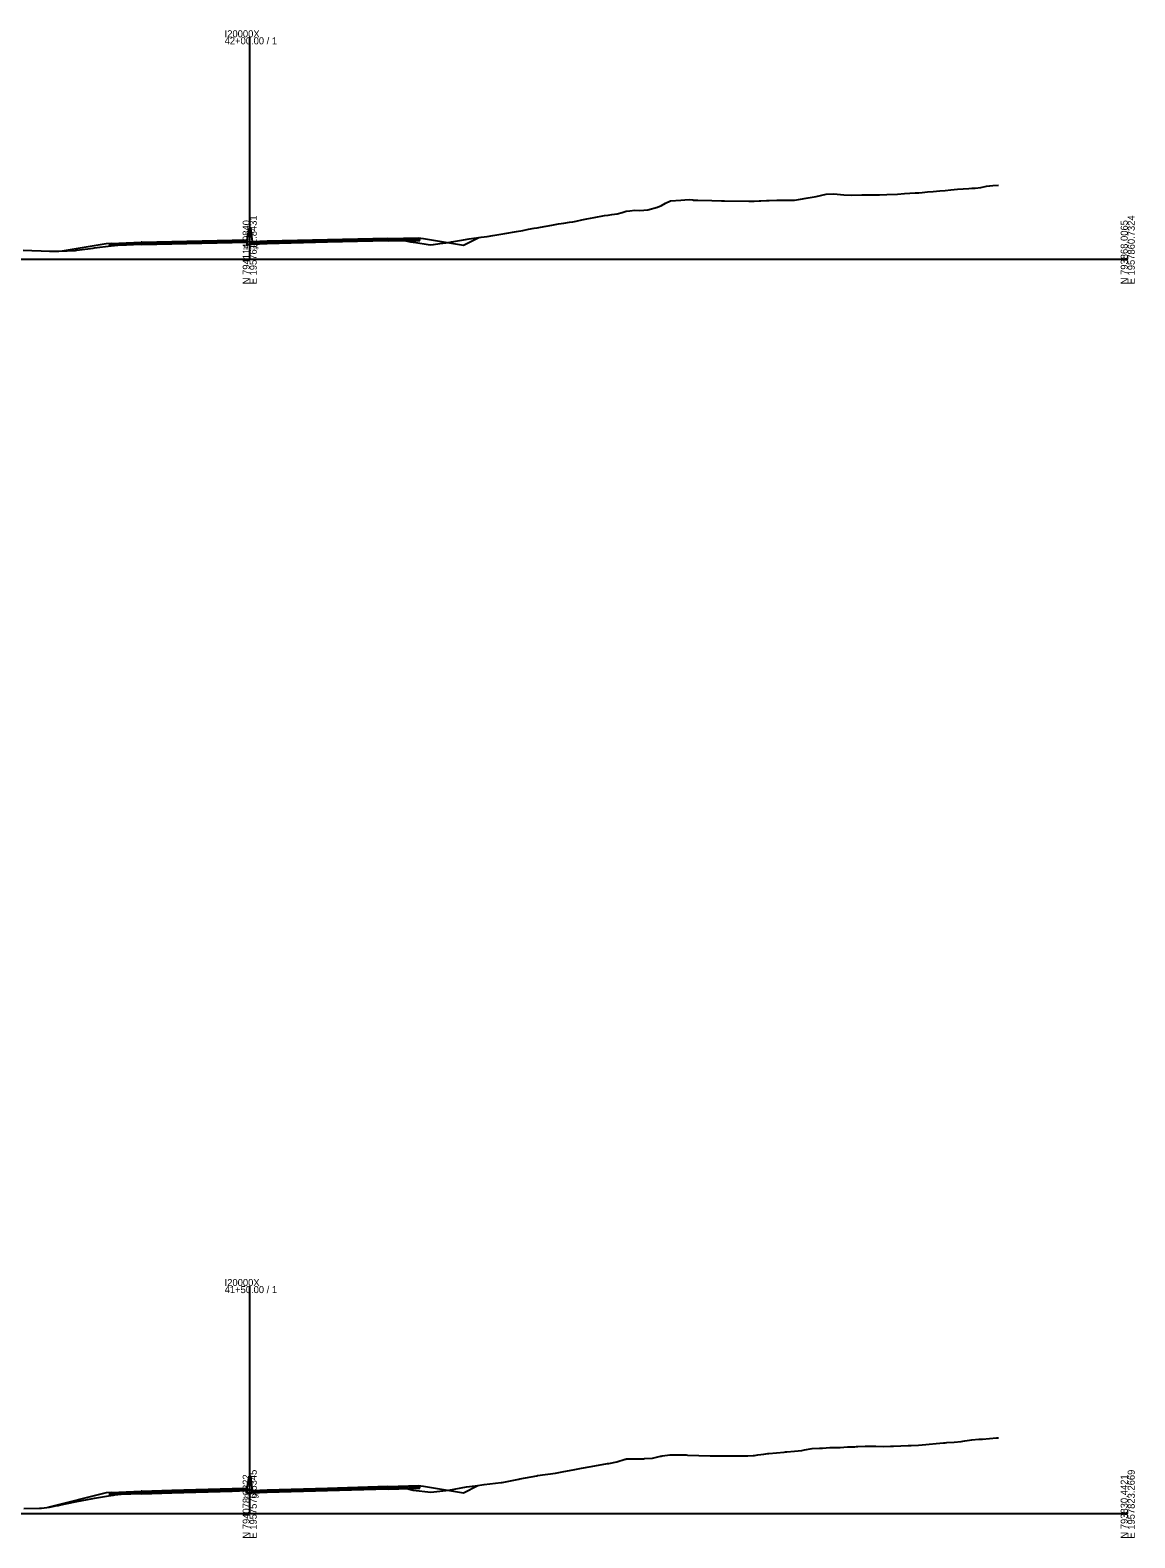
# Model space of a CAD drawing. Extents: x -4026 to 9638, y -10 to 19609.
# Drawn here: x -2738 to -2297, y 11490 to 12091 of the extents above; entities that cross this region are included whole.
import ezdxf

# ---------------------------------------------------------------- set-up
doc = ezdxf.new("R2010")
doc.units = 0
for name, color, linetype in [('RD_GPK_XS_Cell', 7, 'Continuous'), ('RD_XS_Base', 7, 'Continuous'), ('RD_XS_ExGround', 7, 'Continuous'), ('RD_XS_Greenside', 7, 'Continuous'), ('RD_XS_MedBWall', 7, 'Continuous'), ('RD_XS_Pave', 7, 'Continuous'), ('RD_XS_PaveOvlay', 7, 'Continuous'), ('RD_XS_TieSlope', 7, 'Continuous'), ('RD_XS_TX_Elev_EX', 7, 'Continuous')]:
    doc.layers.add(name, color=color, linetype=linetype)

msp = doc.modelspace()

# ---------------------------------------------------------------- linework, layer by layer
at = {"layer": 'RD_GPK_XS_Cell'}
for p, q in [((-2650, 12000), (-2650, 12088.48)), ((-3000, 12000), (-2650, 12000)), ((-2650, 12000), (-2300, 12000)), ((-2650, 11500), (-2650, 11590.67)), ((-3000, 11500), (-2650, 11500)), ((-2650, 11500), (-2300, 11500))]:
    msp.add_line(p, q, dxfattribs=at)
at = {"layer": 'RD_XS_Base'}
for points in [[(-2705.75, 12005.99), (-2705.25, 12006.01), (-2693.25, 12006.48)], [(-2705.75, 12005.32), (-2705.75, 12005.99)], [(-2693.25, 12005.81), (-2705.75, 12005.32)], [(-2693.25, 12006.48), (-2693, 12006.49)], [(-2693.25, 12005.81), (-2693.25, 12006.48)], [(-2693, 12005.82), (-2693.25, 12005.81)], [(-2657, 12007.33), (-2681, 12006.78), (-2693, 12006.49)], [(-2693, 12005.82), (-2681, 12006.11), (-2657, 12006.66)], [(-2693, 12006.49), (-2693, 12005.82)], [(-2651, 12007.43), (-2657, 12007.33)], [(-2657, 12007.33), (-2657, 12006.66)], [(-2657, 12006.66), (-2651, 12006.76)], [(-2651, 12006.76), (-2651, 12007.43)], [(-2649, 12006.61), (-2643, 12006.86)], [(-2649, 12005.94), (-2649, 12006.61)], [(-2643, 12006.19), (-2649, 12005.94)], [(-2643, 12006.86), (-2619, 12007.42), (-2595, 12007.98)], [(-2595, 12007.31), (-2619, 12006.75), (-2643, 12006.19)], [(-2643, 12006.19), (-2643, 12006.86)], [(-2595, 12007.98), (-2594.75, 12007.98)], [(-2595, 12007.31), (-2595, 12007.98)], [(-2594.75, 12007.31), (-2595, 12007.31)], [(-2582.25, 12008.17), (-2582.75, 12008.16), (-2594.75, 12007.98)], [(-2594.75, 12007.98), (-2594.75, 12007.31)], [(-2594.75, 12007.31), (-2582.25, 12007.5)], [(-2582.25, 12007.5), (-2582.25, 12008.17)], [(-2657, 11509.65), (-2681, 11508.94), (-2693, 11508.57)], [(-2651, 11509.84), (-2657, 11509.65)], [(-2657, 11509.65), (-2657, 11508.98)], [(-2651, 11509.17), (-2651, 11509.84)], [(-2643, 11508.99), (-2619, 11509.71), (-2595, 11510.43)], [(-2595, 11509.76), (-2619, 11509.04), (-2643, 11508.32)], [(-2595, 11510.43), (-2594.75, 11510.43)], [(-2595, 11509.76), (-2595, 11510.43)], [(-2594.75, 11509.76), (-2595, 11509.76)], [(-2582.25, 11510.81), (-2582.75, 11510.8), (-2594.75, 11510.43)], [(-2594.75, 11510.43), (-2594.75, 11509.76)], [(-2594.75, 11509.76), (-2582.25, 11510.14)], [(-2582.25, 11510.14), (-2582.25, 11510.81)], [(-2705.75, 11508.07), (-2705.25, 11508.09), (-2693.25, 11508.56)], [(-2705.75, 11507.4), (-2705.75, 11508.07)], [(-2693.25, 11507.89), (-2705.75, 11507.4)], [(-2693.25, 11508.56), (-2693, 11508.57)], [(-2693.25, 11507.89), (-2693.25, 11508.56)], [(-2693, 11507.9), (-2693.25, 11507.89)], [(-2693, 11507.9), (-2681, 11508.27), (-2657, 11508.98)], [(-2693, 11508.57), (-2693, 11507.9)], [(-2657, 11508.98), (-2651, 11509.17)], [(-2649, 11508.74), (-2643, 11508.99)], [(-2649, 11508.07), (-2649, 11508.74)], [(-2643, 11508.32), (-2649, 11508.07)], [(-2643, 11508.32), (-2643, 11508.99)]]:
    msp.add_lwpolyline(points, dxfattribs=at)
at = {"layer": 'RD_XS_ExGround'}
for points in [[(-2740.27, 12003.64), (-2736.88, 12003.55), (-2733.16, 12003.41), (-2729.8, 12003.28), (-2726.05, 12003.19), (-2719.46, 12003.54), (-2718.93, 12003.6), (-2712.43, 12004.45), (-2711.82, 12004.53), (-2705.4, 12005.39), (-2705.06, 12005.43), (-2704.33, 12005.47), (-2703.92, 12005.5), (-2702.52, 12005.57), (-2699.07, 12005.74), (-2693.47, 12005.99), (-2689.83, 12006.16), (-2679.66, 12006.47), (-2678.88, 12006.49), (-2677.9, 12006.52), (-2667.07, 12006.81), (-2658.95, 12007.01), (-2655.28, 12007.1), (-2650, 12006.96), (-2649.67, 12006.95), (-2649.31, 12006.92), (-2645.65, 12006.63), (-2641.31, 12006.92), (-2640.52, 12006.97), (-2635.69, 12007.12), (-2628.35, 12007.34), (-2622.45, 12007.49), (-2616.83, 12007.64), (-2614.55, 12007.7), (-2605.28, 12007.93), (-2599.83, 12007.97), (-2597.12, 12007.99), (-2595.29, 12007.92), (-2593.96, 12007.86), (-2593.38, 12007.84), (-2591.92, 12007.77), (-2590.93, 12007.68), (-2588.38, 12007.48), (-2585.87, 12006.99), (-2584.85, 12006.8), (-2583.81, 12006.63), (-2578.83, 12005.93), (-2577.77, 12005.75), (-2576.7, 12005.94), (-2574.24, 12006.25), (-2571.8, 12006.58), (-2570.7, 12006.73), (-2569.59, 12006.92), (-2567.17, 12007.3), (-2564.77, 12007.68), (-2562.48, 12008.09), (-2557.74, 12008.83), (-2556.56, 12008.94), (-2555.37, 12009.11), (-2553.03, 12009.48), (-2550.71, 12009.83), (-2548.26, 12010.26), (-2543.68, 12011.02), (-2541.14, 12011.47), (-2538.88, 12011.94), (-2536.65, 12012.33), (-2535.35, 12012.56), (-2534.03, 12012.79), (-2531.81, 12013.22), (-2529.62, 12013.61), (-2526.92, 12014.06), (-2524.74, 12014.38), (-2522.58, 12014.74), (-2521.2, 12014.95), (-2519.81, 12015.24), (-2517.67, 12015.66), (-2515.55, 12016.09), (-2512.7, 12016.64), (-2508.52, 12017.38), (-2507.06, 12017.61), (-2505.59, 12017.8), (-2503.53, 12018.11), (-2501.49, 12018.69), (-2499.99, 12019.13), (-2498.48, 12019.28), (-2496.46, 12019.51), (-2494.46, 12019.49), (-2492.92, 12019.5), (-2491.36, 12019.67), (-2487.43, 12020.71), (-2485.85, 12021.43), (-2484.25, 12022.29), (-2482.31, 12023.24), (-2478.17, 12023.57), (-2476.53, 12023.7), (-2474.53, 12023.84), (-2473.39, 12023.67), (-2473.07, 12023.61), (-2471.32, 12023.57), (-2465.74, 12023.42), (-2461.96, 12023.32), (-2460.78, 12023.29), (-2450.98, 12023.16), (-2448.91, 12023.12), (-2446.96, 12023.25), (-2446.24, 12023.3), (-2444.02, 12023.42), (-2442.9, 12023.46), (-2439.89, 12023.59), (-2438.21, 12023.6), (-2436.35, 12023.56), (-2434.47, 12023.56), (-2432.82, 12023.6), (-2431.18, 12023.88), (-2427.36, 12024.47), (-2424.15, 12024.96), (-2420.25, 12025.9), (-2417.12, 12026.12), (-2413.14, 12025.64), (-2410.08, 12025.55), (-2406.02, 12025.63), (-2403.05, 12025.63), (-2398.91, 12025.64), (-2396.02, 12025.75), (-2391.8, 12025.96), (-2388.99, 12026.15), (-2384.69, 12026.44), (-2383.32, 12026.53), (-2381.96, 12026.62), (-2379.78, 12026.84), (-2377.58, 12027.03), (-2376.25, 12027.17), (-2374.93, 12027.27), (-2372.71, 12027.45), (-2370.47, 12027.66), (-2369.17, 12027.77), (-2367.9, 12027.89), (-2365.64, 12028.05), (-2363.35, 12028.22), (-2362.1, 12028.3), (-2360.87, 12028.38), (-2358.57, 12028.56), (-2356.24, 12029.09), (-2355.03, 12029.31), (-2353.83, 12029.4), (-2351.5, 12029.49)], [(-2740.05, 11501.99), (-2733.81, 11502.11), (-2733.41, 11502.09), (-2733, 11502.13), (-2729.87, 11502.54), (-2726.72, 11503.17), (-2726.33, 11503.26), (-2725.95, 11503.33), (-2719.63, 11504.62), (-2718.9, 11504.75), (-2712.54, 11505.96), (-2711.85, 11506.09), (-2705.44, 11507.24), (-2705.12, 11507.28), (-2704.32, 11507.36), (-2703.73, 11507.41), (-2699.99, 11507.79), (-2699.18, 11507.87), (-2697.85, 11507.93), (-2689.71, 11508.31), (-2678.92, 11508.66), (-2667.23, 11508.99), (-2666.89, 11509), (-2666.52, 11509.01), (-2655.3, 11509.29), (-2652.01, 11509.26), (-2650, 11509.25), (-2649.7, 11509.24), (-2648.1, 11509.09), (-2645.69, 11508.88), (-2642.04, 11509.13), (-2640.54, 11509.24), (-2634.34, 11509.44), (-2628.32, 11509.63), (-2624.94, 11509.71), (-2616.77, 11509.92), (-2608.81, 11510.15), (-2605.33, 11510.25), (-2603, 11510.28), (-2597.07, 11510.35), (-2591.96, 11510.49), (-2588.45, 11510.22), (-2584.87, 11509.38), (-2577.77, 11508.58), (-2570.68, 11509.26), (-2563.59, 11510.68), (-2560.16, 11510.98), (-2556.5, 11511.56), (-2549.71, 11512.37), (-2549.4, 11512.41), (-2542.66, 11513.76), (-2542.31, 11513.82), (-2535.61, 11515.04), (-2535.22, 11515.1), (-2528.13, 11516.11), (-2524.81, 11516.71), (-2521.03, 11517.41), (-2517.74, 11518.11), (-2513.94, 11518.81), (-2507.41, 11519.9), (-2506.85, 11519.98), (-2503.59, 11520.56), (-2500.36, 11521.64), (-2500.06, 11521.71), (-2499.75, 11521.74), (-2493.31, 11521.85), (-2492.99, 11521.87), (-2492.66, 11521.91), (-2489.45, 11522.08), (-2486.26, 11522.86), (-2485.92, 11522.93), (-2485.57, 11522.98), (-2482.38, 11523.42), (-2478.03, 11523.44), (-2477.16, 11523.42), (-2475.96, 11523.34), (-2475.47, 11523.29), (-2466.46, 11523.06), (-2462.88, 11522.97), (-2455.39, 11522.95), (-2451.38, 11522.95), (-2449.34, 11523.12), (-2448.82, 11523.17), (-2447.51, 11523.36), (-2445.06, 11523.73), (-2444.21, 11523.85), (-2443.49, 11523.95), (-2443.01, 11523.99), (-2436.91, 11524.49), (-2436.42, 11524.54), (-2435.92, 11524.6), (-2432.88, 11524.91), (-2429.87, 11525.19), (-2428.83, 11525.35), (-2425.81, 11525.92), (-2422.82, 11526.08), (-2422.28, 11526.11), (-2421.73, 11526.11), (-2418.74, 11526.32), (-2415.77, 11526.32), (-2415.21, 11526.34), (-2414.64, 11526.35), (-2411.67, 11526.55), (-2408.72, 11526.61), (-2408.13, 11526.69), (-2407.55, 11526.69), (-2404.6, 11526.89), (-2401.67, 11526.87), (-2401.06, 11526.85), (-2400.46, 11526.84), (-2397.53, 11526.76), (-2394.62, 11526.82), (-2393.99, 11526.83), (-2393.36, 11526.84), (-2387.57, 11527.07), (-2386.27, 11527.13), (-2383.39, 11527.26), (-2380.52, 11527.54), (-2379.18, 11527.67), (-2376.31, 11527.96), (-2373.47, 11528.16), (-2372.78, 11528.22), (-2372.09, 11528.26), (-2369.24, 11528.44), (-2366.42, 11528.77), (-2365.71, 11528.85), (-2364.99, 11528.97), (-2362.17, 11529.41), (-2359.37, 11529.61), (-2358.64, 11529.67), (-2357.9, 11529.7), (-2355.1, 11529.85), (-2352.32, 11530.15), (-2351.57, 11530.22)]]:
    msp.add_lwpolyline(points, dxfattribs=at)
at = {"layer": 'RD_XS_Greenside'}
for points in [[(-2582.75, 12008.49), (-2580.75, 12008.33)], [(-2580.75, 12008.33), (-2564.75, 12005.66)], [(-2707.25, 12006.18), (-2724.81, 12003.25)], [(-2705.25, 12006.34), (-2707.25, 12006.18)], [(-2582.75, 11511.13), (-2580.75, 11510.96)], [(-2580.75, 11510.96), (-2564.75, 11508.3)], [(-2707.25, 11508.26), (-2730.46, 11502.46)], [(-2705.25, 11508.42), (-2707.25, 11508.26)]]:
    msp.add_lwpolyline(points, dxfattribs=at)
at = {"layer": 'RD_XS_MedBWall'}
for points in [[(-2651, 12007.76), (-2650.25, 12012.43)], [(-2650.25, 12012.43), (-2649.75, 12012.43), (-2649, 12006.94)], [(-2651, 12005.94), (-2651, 12007.43), (-2651, 12007.76)], [(-2649, 12005.94), (-2651, 12005.94)], [(-2649, 12006.94), (-2649, 12006.61), (-2649, 12005.94)], [(-2651, 11510.17), (-2650.25, 11514.84)], [(-2651, 11508.07), (-2651, 11509.84), (-2651, 11510.17)], [(-2650.25, 11514.84), (-2649.75, 11514.84), (-2649, 11509.07)], [(-2649, 11508.07), (-2651, 11508.07)], [(-2649, 11509.07), (-2649, 11508.74), (-2649, 11508.07)]]:
    msp.add_lwpolyline(points, dxfattribs=at)
at = {"layer": 'RD_XS_Pave'}
for points in [[(-2582.75, 12008.33), (-2594.75, 12008.15)], [(-2582.75, 12008.16), (-2582.75, 12008.33)], [(-2705.25, 12006.18), (-2693.25, 12006.65)], [(-2693.25, 12006.48), (-2705.25, 12006.01)], [(-2705.25, 12006.01), (-2705.25, 12006.18)], [(-2693.25, 12006.65), (-2693, 12006.66)], [(-2693.25, 12006.48), (-2693.25, 12006.65)], [(-2693, 12006.49), (-2693.25, 12006.48)], [(-2693, 12006.66), (-2681, 12006.94), (-2657, 12007.5)], [(-2657, 12007.33), (-2681, 12006.78), (-2693, 12006.49)], [(-2693, 12006.66), (-2693, 12006.49)], [(-2657, 12007.5), (-2651, 12007.6)], [(-2657, 12007.5), (-2657, 12007.33)], [(-2651, 12007.43), (-2657, 12007.33)], [(-2651, 12007.6), (-2651, 12007.43)], [(-2643, 12007.03), (-2649, 12006.78)], [(-2649, 12006.61), (-2643, 12006.86)], [(-2649, 12006.78), (-2649, 12006.61)], [(-2595, 12008.15), (-2619, 12007.59), (-2643, 12007.03)], [(-2643, 12006.86), (-2619, 12007.42), (-2595, 12007.98)], [(-2643, 12007.03), (-2643, 12006.86)], [(-2595, 12008.15), (-2594.75, 12008.15)], [(-2595, 12007.98), (-2595, 12008.15)], [(-2594.75, 12007.98), (-2595, 12007.98)], [(-2594.75, 12007.98), (-2582.75, 12008.16)], [(-2594.75, 12008.15), (-2594.75, 12007.98)], [(-2693, 11508.74), (-2681, 11509.1), (-2657, 11509.82)], [(-2657, 11509.65), (-2681, 11508.94), (-2693, 11508.57)], [(-2657, 11509.82), (-2651, 11510.01)], [(-2651, 11509.84), (-2657, 11509.65)], [(-2657, 11509.82), (-2657, 11509.65)], [(-2651, 11510.01), (-2651, 11509.84)], [(-2595, 11510.6), (-2619, 11509.88), (-2643, 11509.16)], [(-2643, 11508.99), (-2619, 11509.71), (-2595, 11510.43)], [(-2595, 11510.6), (-2594.75, 11510.6)], [(-2595, 11510.43), (-2595, 11510.6)], [(-2594.75, 11510.43), (-2595, 11510.43)], [(-2582.75, 11510.96), (-2594.75, 11510.6)], [(-2594.75, 11510.43), (-2582.75, 11510.8)], [(-2594.75, 11510.6), (-2594.75, 11510.43)], [(-2582.75, 11510.8), (-2582.75, 11510.96)], [(-2705.25, 11508.26), (-2693.25, 11508.73)], [(-2693.25, 11508.56), (-2705.25, 11508.09)], [(-2705.25, 11508.09), (-2705.25, 11508.26)], [(-2693.25, 11508.73), (-2693, 11508.74)], [(-2693.25, 11508.56), (-2693.25, 11508.73)], [(-2693, 11508.57), (-2693.25, 11508.56)], [(-2693, 11508.74), (-2693, 11508.57)], [(-2643, 11509.16), (-2649, 11508.91)], [(-2649, 11508.74), (-2643, 11508.99)], [(-2649, 11508.91), (-2649, 11508.74)], [(-2643, 11509.16), (-2643, 11508.99)]]:
    msp.add_lwpolyline(points, dxfattribs=at)
at = {"layer": 'RD_XS_PaveOvlay'}
for points in [[(-2595, 12008.31), (-2619, 12007.75), (-2643, 12007.19)], [(-2595, 12008.31), (-2594.75, 12008.32)], [(-2595, 12008.15), (-2595, 12008.31)], [(-2594.75, 12008.32), (-2582.75, 12008.49)], [(-2582.75, 12008.33), (-2594.75, 12008.15)], [(-2594.75, 12008.32), (-2594.75, 12008.15)], [(-2582.75, 12008.49), (-2582.75, 12008.33)], [(-2705.25, 12006.34), (-2693.25, 12006.82)], [(-2693.25, 12006.65), (-2705.25, 12006.18)], [(-2705.25, 12006.18), (-2705.25, 12006.34)], [(-2693, 12006.83), (-2693.25, 12006.82)], [(-2693.25, 12006.82), (-2693.25, 12006.65)], [(-2693.25, 12006.65), (-2693, 12006.66)], [(-2693, 12006.83), (-2681, 12007.11), (-2657, 12007.67)], [(-2657, 12007.5), (-2681, 12006.94), (-2693, 12006.66)], [(-2693, 12006.66), (-2693, 12006.83)], [(-2657, 12007.67), (-2651, 12007.76)], [(-2657, 12007.67), (-2657, 12007.5)], [(-2651, 12007.6), (-2657, 12007.5)], [(-2651, 12007.76), (-2651, 12007.6)], [(-2643, 12007.19), (-2649, 12006.94)], [(-2649, 12006.78), (-2643, 12007.03)], [(-2649, 12006.94), (-2649, 12006.78)], [(-2643, 12007.03), (-2619, 12007.59), (-2595, 12008.15)], [(-2643, 12007.19), (-2643, 12007.03)], [(-2594.75, 12008.15), (-2595, 12008.15)], [(-2693, 11508.91), (-2681, 11509.27), (-2657, 11509.99)], [(-2657, 11509.82), (-2681, 11509.1), (-2693, 11508.74)], [(-2657, 11509.99), (-2651, 11510.17)], [(-2651, 11510.01), (-2657, 11509.82)], [(-2657, 11509.99), (-2657, 11509.82)], [(-2651, 11510.17), (-2651, 11510.01)], [(-2595, 11510.76), (-2619, 11510.04), (-2643, 11509.32)], [(-2643, 11509.16), (-2619, 11509.88), (-2595, 11510.6)], [(-2595, 11510.76), (-2594.75, 11510.77)], [(-2595, 11510.6), (-2595, 11510.76)], [(-2594.75, 11510.6), (-2595, 11510.6)], [(-2594.75, 11510.77), (-2582.75, 11511.13)], [(-2582.75, 11510.96), (-2594.75, 11510.6)], [(-2594.75, 11510.77), (-2594.75, 11510.6)], [(-2582.75, 11511.13), (-2582.75, 11510.96)], [(-2705.25, 11508.42), (-2693.25, 11508.9)], [(-2693.25, 11508.73), (-2705.25, 11508.26)], [(-2705.25, 11508.26), (-2705.25, 11508.42)], [(-2693, 11508.91), (-2693.25, 11508.9)], [(-2693.25, 11508.9), (-2693.25, 11508.73)], [(-2693.25, 11508.73), (-2693, 11508.74)], [(-2693, 11508.74), (-2693, 11508.91)], [(-2643, 11509.32), (-2649, 11509.07)], [(-2649, 11508.91), (-2643, 11509.16)], [(-2649, 11509.07), (-2649, 11508.91)], [(-2643, 11509.32), (-2643, 11509.16)]]:
    msp.add_lwpolyline(points, dxfattribs=at)
at = {"layer": 'RD_XS_TieSlope'}
for points in [[(-2564.75, 12005.66), (-2558.72, 12008.67)], [(-2564.75, 11508.3), (-2559.02, 11511.16)]]:
    msp.add_lwpolyline(points, dxfattribs=at)

# ---------------------------------------------------------------- texts
at = {"layer": 'RD_GPK_XS_Cell'}
for s, p in [('42+00.00 / 1', (-2660, 12085.68)), ('I20000X', (-2660, 12088.48)), ('41+50.00 / 1', (-2660, 11587.87)), ('I20000X', (-2660, 11590.67))]:
    msp.add_text(s, height=2.8, dxfattribs=at).set_placement(p)
for s, p in [('N 794114.0840', (-2650, 11990)), ('E 1957611.8431', (-2647.2, 11990)), ('N 793868.0065', (-2300, 11990)), ('E 1957860.7324', (-2297.2, 11990)), ('E 1957576.5345', (-2647.2, 11490)), ('E 1957823.2669', (-2297.2, 11490)), ('N 794078.6822', (-2650, 11490)), ('N 793830.4421', (-2300, 11490))]:
    msp.add_text(s, height=2.8, rotation=90, dxfattribs=at).set_placement(p)
at = {"layer": 'RD_XS_TX_Elev_EX'}
for s, p in [('324.96', (-2652.82, 12003.96)), ('325.25', (-2652.69, 11506.25))]:
    msp.add_text(s, height=1.5, dxfattribs=at).set_placement(p)

doc.saveas('drawing.dxf')
